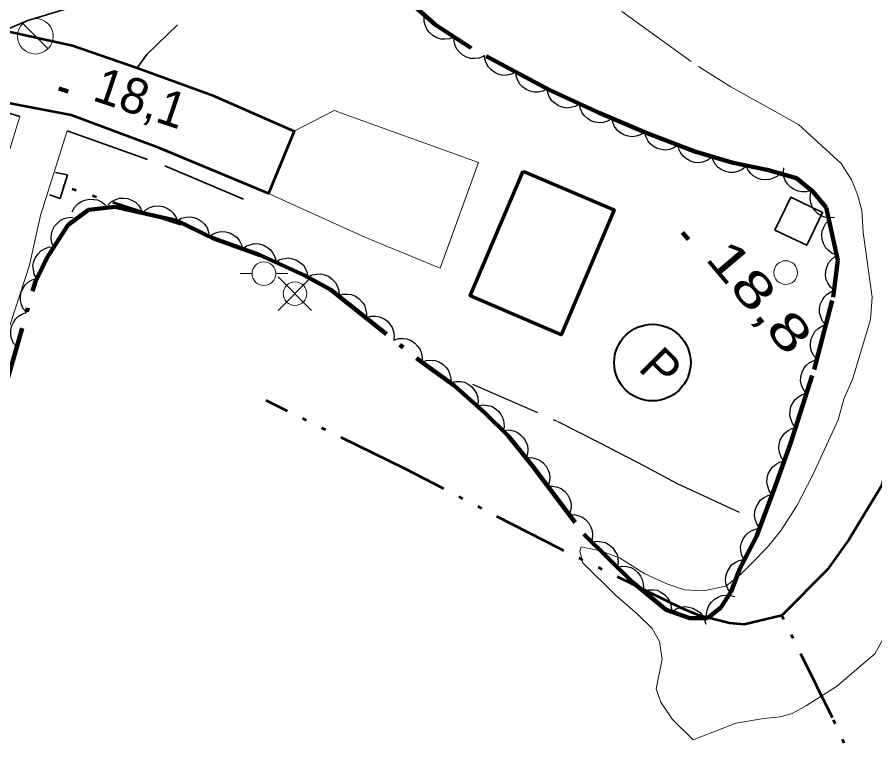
# Model space of a CAD drawing. Extents: x 386081 to 389416, y 5130568 to 5134082.
# Drawn here: x 387861.9 to 387934.2, y 5132226.5 to 5132287.6 of the extents above; entities that cross this region are included whole.
import ezdxf

# ---------------------------------------------------------------- set-up
doc = ezdxf.new("R2010")
doc.units = 0
doc.header["$LTSCALE"] = 1.2
for name, pattern in [('DASH_DOUBLE_DOT', [9.2, 5, -1.2, 0.3, -1.2, 0.3, -1.2]), ('DOT_DASHED', [7.7, 5, -1.2, 0.3, -1.2]), ('LONG_DASHED', [7.5, 6, -1.5]), ('MEDIUM_DASHED', [4.5, 3, -1.5])]:
    doc.linetypes.add(name, pattern=pattern)
for name, color, linetype, lineweight in [('19', 7, 'Continuous', 13), ('2', 7, 'Continuous', 13), ('21', 7, 'LONG_DASHED', 35), ('26', 7, 'Continuous', 35), ('3', 7, 'Continuous', 140), ('31', 7, 'Continuous', 70), ('36', 7, 'Continuous', 13), ('38', 7, 'Continuous', 40), ('4', 7, 'DASH_DOUBLE_DOT', 53), ('41', 7, 'DOT_DASHED', 25), ('44', 7, 'Continuous', 25)]:
    doc.layers.add(name, color=color, linetype=linetype, lineweight=lineweight)

msp = doc.modelspace()

# ---------------------------------------------------------------- linework, layer by layer
at = {"layer": '19'}
for points in [[(387883.05, 5132272.71), (387891.17, 5132269.01), (387897.52, 5132266.41), (387900.75, 5132275.32), (387888.61, 5132279.68), (387885.24, 5132277.96)], [(387862.12, 5132279.18), (387861.04, 5132275.72), (387858.91, 5132269.84), (387856.33, 5132263.57), (387852.29, 5132254.68), (387857.11, 5132252.3), (387860.88, 5132260.38), (387862.93, 5132266.67), (387863.84, 5132270.84), (387866.09, 5132277.99)]]:
    msp.add_lwpolyline(points, dxfattribs=at)
at = {"layer": '2', "linetype": 'LONG_DASHED'}
msp.add_lwpolyline([(387912.83, 5132288.04), (387919.29, 5132283.39), (387922.02, 5132281.69), (387927.73, 5132278.52), (387931.33, 5132275.22), (387932.2, 5132273.86), (387932.69, 5132272.63), (387933.06, 5132271.27), (387933.18, 5132269.41), (387933.92, 5132263.96), (387933.8, 5132262.1), (387932.3, 5132257.12), (387931.55, 5132255.37), (387931.06, 5132253.63), (387928.94, 5132249.01), (387927.57, 5132246.39), (387926.2, 5132244.27), (387925.08, 5132242.89), (387923.84, 5132241.63), (387922.72, 5132240.5), (387921.6, 5132239.62), (387919.73, 5132239.23), (387918.12, 5132239.33), (387916.62, 5132239.81), (387914.76, 5132240.66), (387912.65, 5132242), (387911.03, 5132242.6), (387909.42, 5132242.95), (387909.29, 5132242.58), (387909.54, 5132241.59), (387912.27, 5132238.89), (387914.14, 5132237.3), (387915.38, 5132236.07), (387916, 5132234.96), (387916.24, 5132233.47), (387915.74, 5132230.98), (387916.11, 5132229.87), (387917.11, 5132228.39), (387918.85, 5132226.68), (387922.45, 5132228.09), (387924.81, 5132228.49), (387926.18, 5132228.63), (387927.18, 5132228.89), (387928.41, 5132229.58)], dxfattribs=at)
at = {"layer": '2'}
msp.add_lwpolyline([(387949.58, 5132277.24), (387946.72, 5132273.4), (387945.48, 5132271.16), (387944.23, 5132268.42), (387942.24, 5132261.95), (387941.12, 5132254.86), (387940.74, 5132251.26), (387939.61, 5132244.67), (387938.87, 5132241.44), (387935.13, 5132235.69), (387934.14, 5132233.94), (387930.91, 5132231.17), (387928.41, 5132229.58)], dxfattribs=at)
at = {"layer": '21', "linetype": 'MEDIUM_DASHED'}
for points in [[(387860.78, 5132286.44), (387862.78, 5132287.28), (387865.84, 5132288.2), (387868.86, 5132289.23), (387870.95, 5132290.29), (387873.09, 5132291.74), (387875.38, 5132293.66), (387881.62, 5132300.01), (387887.6, 5132305.78), (387894.9, 5132314.12), (387902.8, 5132322.8), (387912.7, 5132332.94), (387922.03, 5132342.34), (387944.62, 5132364.16), (387960.02, 5132379.36), (387967.89, 5132387.55), (387974.37, 5132394.99), (387979.87, 5132401.66), (387990.47, 5132414.87), (387993.62, 5132418.08), (388000.82, 5132427.01), (388006.82, 5132435.09), (388017.51, 5132449)], [(387871.99, 5132283.29), (387872.81, 5132284.42), (387877.34, 5132288.8), (387880.16, 5132291.8), (387883.3, 5132295.45), (387886.81, 5132298.67), (387899.44, 5132312.84), (387911.12, 5132325.44), (387921.28, 5132335.78), (387930.99, 5132345.34), (387944.01, 5132357.8), (387957.3, 5132370.29), (387966.89, 5132380.09), (387975.16, 5132389.32), (387982.37, 5132397.55), (387987.94, 5132404.97), (387994.4, 5132413.8), (388000.29, 5132420), (388012.45, 5132436.38), (388020.46, 5132446.74)]]:
    msp.add_lwpolyline(points, dxfattribs=at)
at = {"layer": '21', "linetype": 'Continuous', "lineweight": 53}
msp.add_lwpolyline([(387763.15, 5132287.28), (387788.03, 5132285.2), (387808.99, 5132285.22), (387825.16, 5132285.86), (387836.05, 5132286.38), (387851.38, 5132286.8), (387855.95, 5132286.84), (387860.78, 5132286.44), (387866.55, 5132285.16), (387871.99, 5132283.29), (387878.32, 5132280.98), (387885.24, 5132277.96), (387883.05, 5132272.71), (387873.82, 5132276.54), (387866.45, 5132279.3), (387860.09, 5132280.5), (387854.1, 5132281), (387848.16, 5132280.97), (387838.97, 5132280.51), (387813.71, 5132278.82), (387800.16, 5132278.67), (387785.48, 5132279.18), (387766.83, 5132280.38)], dxfattribs=at)
at = {"layer": '21'}
for points in [[(387812.02, 5132278.07), (387815.64, 5132278.11), (387828.06, 5132278.98), (387844.65, 5132279.8), (387849.76, 5132279.92), (387856.3, 5132280.01), (387861.29, 5132279.43), (387862.12, 5132279.18)], [(387866.09, 5132277.99), (387874.32, 5132275.04), (387881.32, 5132272.07)]]:
    msp.add_lwpolyline(points, dxfattribs=at)
at = {"layer": '26'}
for p, q in [((387866.12, 5132274.28), (387865.12, 5132274.48)), ((387866.12, 5132274.28), (387865.52, 5132272.28)), ((387865.79, 5132273.18), (387865.7, 5132273.21)), ((387865.85, 5132273.38), (387865.75, 5132273.4)), ((387865.85, 5132273.38), (387865.79, 5132273.18)), ((387865.52, 5132272.28), (387864.62, 5132272.58))]:
    msp.add_line(p, q, dxfattribs=at)
at = {"layer": '3'}
for p, q in [((387865.41, 5132281.55), (387866.17, 5132281.29)), ((387917.94, 5132269.43), (387918.45, 5132268.82))]:
    msp.add_line(p, q, dxfattribs=at)
at = {"layer": '31'}
msp.add_lwpolyline([(387904.53, 5132274.59), (387912.2, 5132271.33), (387907.72, 5132260.8), (387900.05, 5132264.07)], close=True, dxfattribs=at)
at = {"layer": '31', "lineweight": 35}
msp.add_lwpolyline([(387925.74, 5132269.62), (387928.42, 5132268.34), (387929.75, 5132271.11), (387927.07, 5132272.39)], close=True, dxfattribs=at)
at = {"layer": '36'}
for p, q in [((387864.49, 5132284.88), (387862.37, 5132287.02)), ((387880.68, 5132265.95), (387881.68, 5132265.95)), ((387884.68, 5132265.95), (387883.68, 5132265.95)), ((387886.7, 5132262.85), (387883.88, 5132265.67)), ((387883.88, 5132262.85), (387886.7, 5132265.67))]:
    msp.add_line(p, q, dxfattribs=at)
for centre, radius in [((387863.42, 5132285.951), 1.5), ((387882.674, 5132265.95), 1), ((387926.644, 5132266.037), 1), ((387885.294, 5132264.265), 1)]:
    msp.add_circle(centre, radius, dxfattribs=at)
at = {"layer": '38'}
msp.add_circle((387915.414, 5132258.458), 3.226, dxfattribs=at)
at = {"layer": '4'}
msp.add_line((387875.64, 5132270.09), (387865.82, 5132273.28), dxfattribs=at)
for points in [[(387900.8, 5132309.92), (387903.08, 5132308.16), (387910.59, 5132304.99), (387919.35, 5132301.95), (387939.96, 5132295.61), (387941.2, 5132294.34), (387941.56, 5132292.55), (387938.27, 5132281.68), (387937.1, 5132271.81), (387937.03, 5132266.91), (387937.28, 5132262.82), (387937.15, 5132259.34), (387936.71, 5132255.8), (387935.77, 5132251.89), (387934.71, 5132248.09), (387931.98, 5132243.59), (387930.17, 5132241.03), (387926.32, 5132237.16)], [(387768.31, 5132040.16), (387781.74, 5132053.34), (387831.18, 5132100.17), (387854.06, 5132122.55), (387874.02, 5132141.51), (387892.64, 5132159.76), (387908.87, 5132175.34), (387924.74, 5132191.25), (387934.74, 5132201.76), (387937.36, 5132206.71), (387937.47, 5132211.61), (387934.69, 5132219.63), (387930.59, 5132228.55), (387926.32, 5132237.16), (387923.15, 5132236.41), (387921.9, 5132236.52), (387919.36, 5132237.17), (387917.87, 5132237.78), (387907.65, 5132242.76), (387894.57, 5132249.5), (387882.86, 5132255.26)]]:
    msp.add_lwpolyline(points, dxfattribs=at)
at = {"layer": '41'}
msp.add_lwpolyline([(387900.24, 5132256.64), (387907.45, 5132253.5), (387911.05, 5132251.68), (387914.78, 5132249.74), (387917.51, 5132248.28), (387922.72, 5132245.86)], dxfattribs=at)
at = {"layer": '44', "linetype": 'DOT_DASHED', "lineweight": 90}
msp.add_lwpolyline([(387860.66, 5132255.58), (387863.42, 5132265.3), (387864.42, 5132267.3), (387866.17, 5132270.05), (387867.91, 5132271.32), (387870.15, 5132271.59), (387875.38, 5132270.41), (387878.37, 5132268.95), (387882.35, 5132267.5), (387886.08, 5132265.81), (387888.32, 5132264.59), (387895.98, 5132258.49), (387898.71, 5132256.54), (387901.32, 5132254.21), (387903.3, 5132252.25), (387905.29, 5132249.79), (387909.63, 5132244.01), (387913.73, 5132239.96), (387916.58, 5132237.64), (387918.57, 5132236.92), (387920.06, 5132236.93), (387921.18, 5132237.82), (387922.05, 5132239.19), (387922.8, 5132241.18), (387924.17, 5132243.81), (387925.67, 5132247.79), (387927.04, 5132251.65), (387929.03, 5132257.88), (387930.65, 5132263.97), (387931.03, 5132267.08), (387930.04, 5132271.53), (387928.92, 5132272.88), (387927.56, 5132273.98), (387925.08, 5132274.7), (387922.22, 5132275.29), (387918.99, 5132276.24), (387914.9, 5132277.81), (387910.92, 5132279.5), (387906.7, 5132281.44), (387900.12, 5132284.97), (387897.14, 5132286.92), (387894.78, 5132289)], dxfattribs=at)
at = {"layer": '44'}
for points in [[(387898.7, 5132285.9), (387898.31, 5132285.74), (387897.91, 5132285.7), (387897.58, 5132285.71), (387897.24, 5132285.82), (387896.92, 5132286), (387896.64, 5132286.26), (387896.42, 5132286.5), (387896.28, 5132286.82), (387896.19, 5132287.18), (387896.19, 5132287.54)], [(387901.21, 5132284.26), (387900.82, 5132284.1), (387900.42, 5132284.06), (387900.09, 5132284.07), (387899.75, 5132284.18), (387899.43, 5132284.35), (387899.15, 5132284.61), (387898.93, 5132284.86), (387898.79, 5132285.18), (387898.7, 5132285.54), (387898.7, 5132285.9)], [(387903.91, 5132282.94), (387903.54, 5132282.74), (387903.14, 5132282.67), (387902.81, 5132282.65), (387902.47, 5132282.73), (387902.13, 5132282.88), (387901.82, 5132283.11), (387901.59, 5132283.34), (387901.42, 5132283.65), (387901.3, 5132284), (387901.26, 5132284.36)], [(387906.55, 5132281.52), (387906.18, 5132281.33), (387905.78, 5132281.25), (387905.45, 5132281.23), (387905.11, 5132281.31), (387904.77, 5132281.46), (387904.47, 5132281.69), (387904.23, 5132281.92), (387904.07, 5132282.23), (387903.94, 5132282.58), (387903.91, 5132282.94)], [(387909.27, 5132280.26), (387908.92, 5132280.04), (387908.52, 5132279.94), (387908.19, 5132279.9), (387907.85, 5132279.96), (387907.5, 5132280.09), (387907.18, 5132280.3), (387906.93, 5132280.51), (387906.75, 5132280.81), (387906.61, 5132281.16), (387906.55, 5132281.51)], [(387912, 5132279), (387911.64, 5132278.79), (387911.25, 5132278.69), (387910.92, 5132278.65), (387910.57, 5132278.71), (387910.22, 5132278.83), (387909.91, 5132279.05), (387909.66, 5132279.26), (387909.47, 5132279.56), (387909.33, 5132279.9), (387909.27, 5132280.26)], [(387914.77, 5132277.86), (387914.42, 5132277.64), (387914.03, 5132277.52), (387913.71, 5132277.48), (387913.36, 5132277.53), (387913.01, 5132277.64), (387912.68, 5132277.85), (387912.43, 5132278.05), (387912.23, 5132278.34), (387912.08, 5132278.68), (387912.01, 5132279.04)], [(387917.57, 5132276.78), (387917.23, 5132276.54), (387916.84, 5132276.42), (387916.52, 5132276.36), (387916.17, 5132276.4), (387915.81, 5132276.5), (387915.48, 5132276.69), (387915.22, 5132276.89), (387915.02, 5132277.18), (387914.85, 5132277.51), (387914.77, 5132277.86)], [(387920.37, 5132275.71), (387920.03, 5132275.47), (387919.64, 5132275.34), (387919.32, 5132275.28), (387918.97, 5132275.32), (387918.61, 5132275.42), (387918.28, 5132275.62), (387918.02, 5132275.81), (387917.82, 5132276.1), (387917.65, 5132276.43), (387917.57, 5132276.78)], [(387923.29, 5132274.98), (387922.97, 5132274.71), (387922.59, 5132274.55), (387922.27, 5132274.47), (387921.92, 5132274.48), (387921.56, 5132274.55), (387921.21, 5132274.72), (387920.94, 5132274.89), (387920.71, 5132275.16), (387920.52, 5132275.48), (387920.41, 5132275.82)], [(387926.25, 5132274.46), (387925.95, 5132274.17), (387925.59, 5132273.98), (387925.28, 5132273.87), (387924.93, 5132273.85), (387924.56, 5132273.89), (387924.2, 5132274.03), (387923.91, 5132274.18), (387923.66, 5132274.43), (387923.45, 5132274.73), (387923.31, 5132275.06)], [(387928.81, 5132272.97), (387928.41, 5132272.84), (387928.01, 5132272.84), (387927.68, 5132272.89), (387927.36, 5132273.03), (387927.05, 5132273.24), (387926.8, 5132273.53), (387926.61, 5132273.79), (387926.5, 5132274.13), (387926.45, 5132274.49), (387926.48, 5132274.85)], [(387930.75, 5132270.68), (387930.33, 5132270.64), (387929.93, 5132270.72), (387929.62, 5132270.82), (387929.33, 5132271.03), (387929.08, 5132271.29), (387928.88, 5132271.62), (387928.75, 5132271.92), (387928.71, 5132272.27), (387928.73, 5132272.64), (387928.83, 5132272.99)], [(387866.53, 5132271.15), (387866.73, 5132271.53), (387867.01, 5132271.82), (387867.27, 5132272.02), (387867.59, 5132272.15), (387867.96, 5132272.23), (387868.34, 5132272.21), (387868.66, 5132272.16), (387868.98, 5132272), (387869.28, 5132271.78), (387869.51, 5132271.51)], [(387869.52, 5132271.73), (387869.83, 5132272.02), (387870.19, 5132272.2), (387870.51, 5132272.3), (387870.86, 5132272.32), (387871.22, 5132272.27), (387871.58, 5132272.12), (387871.86, 5132271.97), (387872.11, 5132271.71), (387872.32, 5132271.41), (387872.45, 5132271.07)], [(387872.45, 5132271.07), (387872.75, 5132271.36), (387873.12, 5132271.54), (387873.43, 5132271.64), (387873.78, 5132271.66), (387874.15, 5132271.61), (387874.5, 5132271.46), (387874.79, 5132271.31), (387875.04, 5132271.05), (387875.25, 5132270.75), (387875.38, 5132270.41)], [(387864.97, 5132268.17), (387864.81, 5132268.55), (387864.76, 5132268.95), (387864.77, 5132269.28), (387864.87, 5132269.62), (387865.04, 5132269.95), (387865.3, 5132270.23), (387865.54, 5132270.45), (387865.86, 5132270.59), (387866.22, 5132270.69), (387866.58, 5132270.7)], [(387875.38, 5132270.41), (387875.74, 5132270.62), (387876.14, 5132270.71), (387876.46, 5132270.74), (387876.81, 5132270.67), (387877.15, 5132270.54), (387877.47, 5132270.32), (387877.71, 5132270.1), (387877.89, 5132269.8), (387878.02, 5132269.45), (387878.07, 5132269.1)], [(387930.93, 5132267.52), (387930.54, 5132267.67), (387930.23, 5132267.93), (387930, 5132268.16), (387929.83, 5132268.48), (387929.72, 5132268.83), (387929.7, 5132269.21), (387929.72, 5132269.54), (387929.85, 5132269.87), (387930.03, 5132270.19), (387930.28, 5132270.45)], [(387878.06, 5132269.06), (387878.4, 5132269.31), (387878.78, 5132269.44), (387879.11, 5132269.51), (387879.46, 5132269.47), (387879.81, 5132269.38), (387880.15, 5132269.19), (387880.41, 5132269), (387880.62, 5132268.72), (387880.79, 5132268.39), (387880.88, 5132268.04)], [(387863.54, 5132265.54), (387863.33, 5132265.9), (387863.25, 5132266.3), (387863.22, 5132266.63), (387863.29, 5132266.97), (387863.43, 5132267.31), (387863.65, 5132267.62), (387863.87, 5132267.87), (387864.18, 5132268.04), (387864.52, 5132268.17), (387864.88, 5132268.22)], [(387880.88, 5132268.04), (387881.22, 5132268.28), (387881.6, 5132268.41), (387881.92, 5132268.48), (387882.28, 5132268.45), (387882.63, 5132268.35), (387882.97, 5132268.16), (387883.23, 5132267.97), (387883.44, 5132267.69), (387883.61, 5132267.36), (387883.7, 5132267.01)], [(387883.66, 5132266.91), (387884.01, 5132267.13), (387884.41, 5132267.23), (387884.73, 5132267.27), (387885.08, 5132267.21), (387885.43, 5132267.09), (387885.75, 5132266.87), (387886, 5132266.66), (387886.18, 5132266.37), (387886.33, 5132266.03), (387886.39, 5132265.67)], [(387930.72, 5132264.55), (387930.41, 5132264.82), (387930.19, 5132265.17), (387930.05, 5132265.47), (387930.01, 5132265.82), (387930.02, 5132266.19), (387930.13, 5132266.55), (387930.25, 5132266.85), (387930.48, 5132267.12), (387930.76, 5132267.36), (387931.08, 5132267.53)], [(387886.38, 5132265.65), (387886.75, 5132265.84), (387887.15, 5132265.91), (387887.48, 5132265.93), (387887.82, 5132265.85), (387888.16, 5132265.7), (387888.46, 5132265.46), (387888.69, 5132265.23), (387888.86, 5132264.92), (387888.98, 5132264.57), (387889.01, 5132264.21)], [(387862.67, 5132262.67), (387862.4, 5132262.99), (387862.24, 5132263.36), (387862.16, 5132263.68), (387862.16, 5132264.03), (387862.23, 5132264.39), (387862.4, 5132264.74), (387862.57, 5132265.02), (387862.83, 5132265.25), (387863.15, 5132265.44), (387863.49, 5132265.55)], [(387888.94, 5132264.1), (387889.33, 5132264.22), (387889.74, 5132264.23), (387890.07, 5132264.19), (387890.39, 5132264.05), (387890.7, 5132263.84), (387890.95, 5132263.56), (387891.15, 5132263.29), (387891.25, 5132262.96), (387891.31, 5132262.59), (387891.28, 5132262.23)], [(387930.03, 5132261.63), (387929.75, 5132261.95), (387929.59, 5132262.32), (387929.49, 5132262.64), (387929.49, 5132262.99), (387929.56, 5132263.35), (387929.72, 5132263.7), (387929.88, 5132263.98), (387930.15, 5132264.22), (387930.46, 5132264.41), (387930.8, 5132264.53)], [(387861.85, 5132259.78), (387861.58, 5132260.1), (387861.42, 5132260.48), (387861.34, 5132260.79), (387861.34, 5132261.15), (387861.41, 5132261.51), (387861.58, 5132261.85), (387861.75, 5132262.13), (387862.01, 5132262.36), (387862.33, 5132262.56), (387862.67, 5132262.67)], [(387891.28, 5132262.23), (387891.68, 5132262.36), (387892.09, 5132262.36), (387892.42, 5132262.32), (387892.74, 5132262.18), (387893.05, 5132261.97), (387893.3, 5132261.69), (387893.49, 5132261.42), (387893.6, 5132261.09), (387893.66, 5132260.72), (387893.63, 5132260.36)], [(387929.26, 5132258.74), (387928.98, 5132259.05), (387928.82, 5132259.42), (387928.72, 5132259.74), (387928.72, 5132260.09), (387928.79, 5132260.45), (387928.95, 5132260.8), (387929.11, 5132261.08), (387929.38, 5132261.32), (387929.69, 5132261.52), (387930.03, 5132261.63)], [(387893.63, 5132260.36), (387894.03, 5132260.49), (387894.44, 5132260.49), (387894.76, 5132260.45), (387895.08, 5132260.31), (387895.39, 5132260.1), (387895.65, 5132259.82), (387895.84, 5132259.55), (387895.95, 5132259.22), (387896, 5132258.85), (387895.98, 5132258.49)], [(387895.98, 5132258.49), (387896.37, 5132258.64), (387896.77, 5132258.66), (387897.1, 5132258.64), (387897.43, 5132258.51), (387897.75, 5132258.33), (387898.02, 5132258.05), (387898.23, 5132257.8), (387898.35, 5132257.47), (387898.43, 5132257.11), (387898.42, 5132256.75)], [(387928.39, 5132255.87), (387928.13, 5132256.19), (387927.98, 5132256.57), (387927.9, 5132256.89), (387927.92, 5132257.24), (387928, 5132257.6), (387928.18, 5132257.95), (387928.36, 5132258.22), (387928.63, 5132258.44), (387928.95, 5132258.62), (387929.3, 5132258.72)], [(387898.44, 5132256.78), (387898.85, 5132256.88), (387899.25, 5132256.86), (387899.58, 5132256.8), (387899.89, 5132256.64), (387900.19, 5132256.42), (387900.43, 5132256.12), (387900.6, 5132255.85), (387900.69, 5132255.51), (387900.73, 5132255.14), (387900.68, 5132254.78)], [(387927.47, 5132253.01), (387927.22, 5132253.34), (387927.07, 5132253.71), (387926.99, 5132254.04), (387927.01, 5132254.39), (387927.09, 5132254.75), (387927.26, 5132255.09), (387927.44, 5132255.36), (387927.72, 5132255.58), (387928.04, 5132255.76), (387928.39, 5132255.87)], [(387900.71, 5132254.81), (387901.12, 5132254.89), (387901.52, 5132254.85), (387901.85, 5132254.78), (387902.15, 5132254.6), (387902.44, 5132254.37), (387902.66, 5132254.06), (387902.82, 5132253.77), (387902.89, 5132253.43), (387902.91, 5132253.06), (387902.84, 5132252.7)], [(387902.89, 5132252.75), (387903.31, 5132252.79), (387903.71, 5132252.7), (387904.02, 5132252.59), (387904.3, 5132252.38), (387904.56, 5132252.12), (387904.75, 5132251.78), (387904.88, 5132251.48), (387904.91, 5132251.13), (387904.89, 5132250.76), (387904.78, 5132250.42)], [(387926.51, 5132250.17), (387926.27, 5132250.5), (387926.13, 5132250.89), (387926.06, 5132251.21), (387926.09, 5132251.56), (387926.18, 5132251.92), (387926.37, 5132252.25), (387926.56, 5132252.52), (387926.84, 5132252.73), (387927.17, 5132252.9), (387927.52, 5132252.99)], [(387904.8, 5132250.44), (387905.22, 5132250.46), (387905.62, 5132250.36), (387905.92, 5132250.24), (387906.2, 5132250.02), (387906.45, 5132249.74), (387906.62, 5132249.4), (387906.74, 5132249.1), (387906.76, 5132248.75), (387906.72, 5132248.38), (387906.61, 5132248.04)], [(387925.51, 5132247.34), (387925.26, 5132247.67), (387925.13, 5132248.06), (387925.06, 5132248.38), (387925.09, 5132248.73), (387925.18, 5132249.09), (387925.37, 5132249.42), (387925.56, 5132249.69), (387925.84, 5132249.9), (387926.16, 5132250.07), (387926.51, 5132250.17)], [(387906.61, 5132248.04), (387907.02, 5132248.06), (387907.42, 5132247.96), (387907.72, 5132247.84), (387908, 5132247.62), (387908.25, 5132247.34), (387908.42, 5132247), (387908.54, 5132246.7), (387908.56, 5132246.35), (387908.52, 5132245.98), (387908.41, 5132245.64)], [(387924.44, 5132244.53), (387924.2, 5132244.88), (387924.07, 5132245.26), (387924.01, 5132245.59), (387924.05, 5132245.94), (387924.15, 5132246.29), (387924.34, 5132246.62), (387924.53, 5132246.89), (387924.82, 5132247.09), (387925.15, 5132247.26), (387925.5, 5132247.34)], [(387908.41, 5132245.64), (387908.82, 5132245.66), (387909.22, 5132245.56), (387909.53, 5132245.44), (387909.8, 5132245.22), (387910.05, 5132244.94), (387910.22, 5132244.6), (387910.34, 5132244.3), (387910.36, 5132243.95), (387910.33, 5132243.58), (387910.21, 5132243.24)], [(387923.14, 5132241.84), (387922.94, 5132242.2), (387922.86, 5132242.6), (387922.84, 5132242.93), (387922.92, 5132243.27), (387923.06, 5132243.62), (387923.29, 5132243.92), (387923.51, 5132244.16), (387923.82, 5132244.33), (387924.17, 5132244.46), (387924.53, 5132244.5)], [(387910.32, 5132243.33), (387910.73, 5132243.41), (387911.13, 5132243.37), (387911.45, 5132243.3), (387911.76, 5132243.12), (387912.04, 5132242.89), (387912.26, 5132242.58), (387912.43, 5132242.29), (387912.5, 5132241.95), (387912.52, 5132241.58), (387912.45, 5132241.22)], [(387922, 5132239.06), (387921.76, 5132239.41), (387921.63, 5132239.79), (387921.57, 5132240.12), (387921.61, 5132240.47), (387921.71, 5132240.82), (387921.9, 5132241.15), (387922.09, 5132241.42), (387922.38, 5132241.62), (387922.71, 5132241.79), (387923.06, 5132241.87)], [(387912.45, 5132241.22), (387912.86, 5132241.31), (387913.26, 5132241.27), (387913.59, 5132241.19), (387913.89, 5132241.02), (387914.18, 5132240.78), (387914.4, 5132240.47), (387914.56, 5132240.19), (387914.63, 5132239.84), (387914.65, 5132239.47), (387914.58, 5132239.12)], [(387914.66, 5132239.2), (387915.06, 5132239.32), (387915.47, 5132239.32), (387915.8, 5132239.28), (387916.12, 5132239.13), (387916.42, 5132238.92), (387916.67, 5132238.64), (387916.86, 5132238.37), (387916.97, 5132238.03), (387917.02, 5132237.67), (387916.99, 5132237.31)], [(387920, 5132236.88), (387919.97, 5132237.3), (387920.05, 5132237.69), (387920.17, 5132238), (387920.38, 5132238.29), (387920.65, 5132238.54), (387920.98, 5132238.72), (387921.28, 5132238.85), (387921.63, 5132238.88), (387922, 5132238.85), (387922.35, 5132238.75)], [(387917.07, 5132237.46), (387917.41, 5132237.71), (387917.8, 5132237.84), (387918.12, 5132237.91), (387918.47, 5132237.87), (387918.83, 5132237.78), (387919.16, 5132237.59), (387919.43, 5132237.4), (387919.64, 5132237.12), (387919.81, 5132236.79), (387919.9, 5132236.44)]]:
    msp.add_lwpolyline(points, dxfattribs=at)

# ---------------------------------------------------------------- texts
at = {"layer": '3'}
msp.add_text('18,1   ', height=3, rotation=341.293, dxfattribs=at).set_placement((387868.13, 5132280.59))
at = {"layer": '3', "width": 1.4}
msp.add_text('18,8   ', height=3, rotation=310.294, dxfattribs=at).set_placement((387919.77, 5132267.21))
at = {"layer": '38'}
msp.add_text('P', height=3, rotation=315.272, dxfattribs=at).set_placement((387914.12, 5132257.89))

doc.saveas('drawing.dxf')
